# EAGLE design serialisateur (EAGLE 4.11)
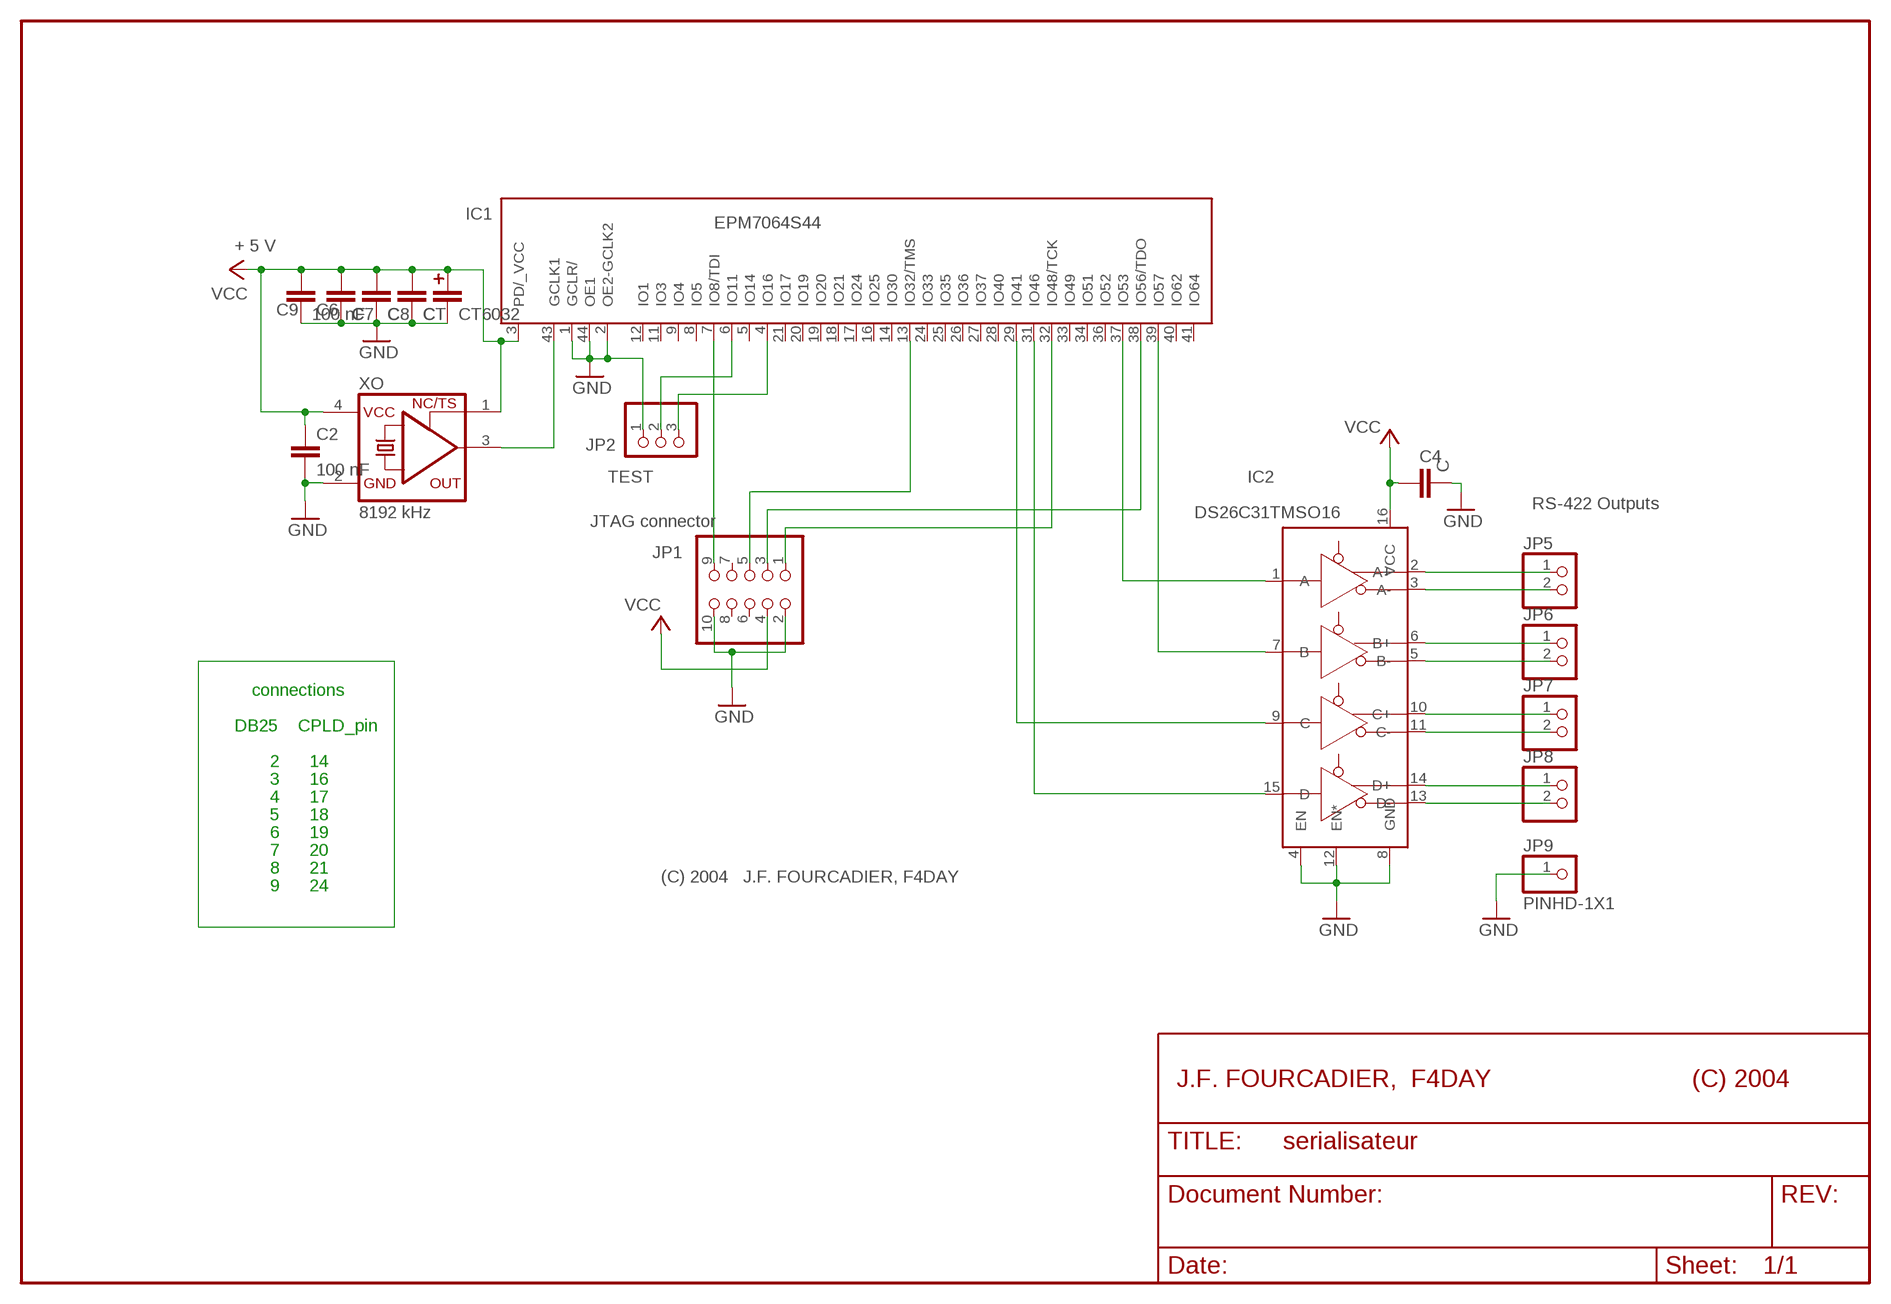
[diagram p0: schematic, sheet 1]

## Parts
C2  100 nF  C1206  [C1206]
C4  C  C1206  [C1206]
C6  C  C1206  [C1206]
C7  C  C1206  [C1206]
C8  C  C1206  [C1206]
C9  100 nF  C1206  [C1206]
CT  CT6032  [CT6032]
IC1  EPM7064S44  EPM7064S44_2  [PLCC-S44_2]
IC2  DS26C31TMSO16  [SO16]
JP1  PINHD-2X5  [2X05]
JP2  PINHD-1X3D  [1X03]
JP5  PINHD-1X2D  [1X02]
JP6  PINHD-1X2D  [1X02]
JP7  PINHD-1X2D  [1X02]
JP8  PINHD-1X2D  [1X02]
JP9  PINHD-1X1  [1X01]
XO  8192 kHz  XO-1100S  [1100S]

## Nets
GND: C2.2 C4.2 C6.2 C7.2 C8.2 C9.2 CT.- IC1.1(GCLR/) IC1.2(OE2-GCLK2) IC1.44(OE1) IC2.4(EN) IC2.8(GND) IC2.12(EN*) JP1.2 JP1.10 JP2.1 JP9.1 XO.2(GND)
N$1: IC1.32(IO48/TCK) JP1.1
N$2: IC1.38(IO56/TDO) JP1.3
N$3: IC1.13(IO32/TMS) JP1.5
N$4: IC1.7(IO8/TDI) JP1.9
N$5: IC1.39(IO57) IC2.7(B)
N$6: IC1.31(IO46) IC2.15(D)
N$7: IC1.37(IO53) IC2.1(A)
N$8: IC2.2(A+) JP5.1
N$9: IC2.3(A-) JP5.2
N$10: IC1.29(IO41) IC2.9(C)
N$11: IC2.6(B+) JP6.1
N$12: IC1.43(GCLK1) XO.3(OUT)
N$13: IC1.4(IO16) JP2.3
N$14: IC1.6(IO11) JP2.2
N$15: IC2.11(C-) JP7.2
N$16: IC2.14(D+) JP8.1
N$17: IC2.13(D-) JP8.2
N$53: IC2.5(B-) JP6.2
N$54: IC2.10(C+) JP7.1
VCC: C2.1 C4.1 C6.1 C7.1 C8.1 C9.1 CT.+ IC1.3(PD/_VCC) IC2.16(VCC) JP1.4 XO.1(TS) XO.4(VCC)
Unconnected: IC1.5(IO14) IC1.8(IO5) IC1.9(IO4) IC1.11(IO3) IC1.12(IO1) IC1.14(IO30) IC1.16(IO25) IC1.17(IO24) IC1.18(IO21) IC1.19(IO20) IC1.20(IO19) IC1.21(IO17) IC1.24(IO33) IC1.25(IO35) IC1.26(IO36) IC1.27(IO37) IC1.28(IO40) IC1.33(IO49) IC1.34(IO51) IC1.36(IO52) IC1.40(IO62) IC1.41(IO64) JP1.6 JP1.7 JP1.8

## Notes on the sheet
- + 5 V
- TEST
- RS-422 Outputs
- JTAG connector
- connections
- DB25    CPLD_pin
- 2      14
- 3      16
- 4      17
- 5      18
- 6      19
- 7      20
- 8      21
- (C) 2004   J.F. FOURCADIER, F4DAY
- 9      24

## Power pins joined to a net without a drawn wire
GND: IC1.10(GND) IC1.22(GND) IC1.30(GND) IC1.42(GND)
VCC: IC1.15(VCC) IC1.23(VCC) IC1.35(VCC)

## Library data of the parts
C2 C4 C6-C9 = capacitor-smd:C
CT = capacitor-smd:CT
IC1 = altera:EPM7064: EPM7064 MAX 7000 family
IC2 = national:DS26C31TM
JP1 = pinhead:PINHD-2X5: PIN HEADER
JP2 = pinhead:PINHD-1X3: PIN HEADER
JP5-JP8 = pinhead:PINHD-1X2: PIN HEADER
JP9 = pinhead:PINHD-1X1: PIN HEADER
XO = crystal:XO-: CRYSTAL

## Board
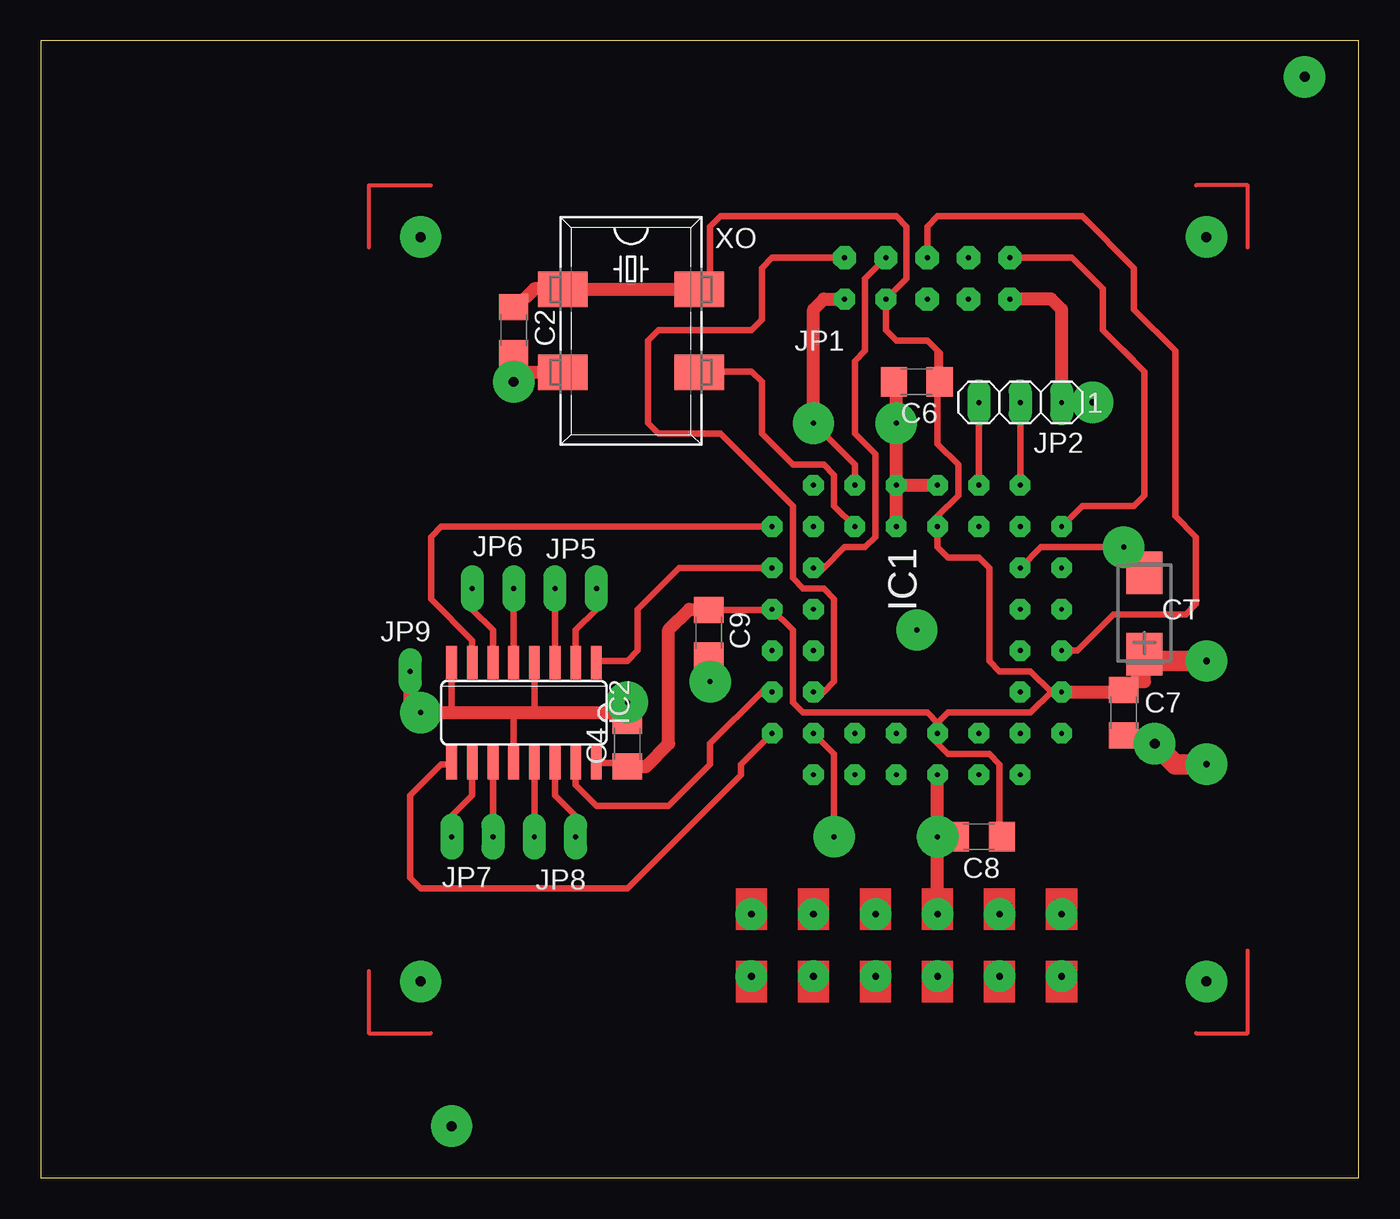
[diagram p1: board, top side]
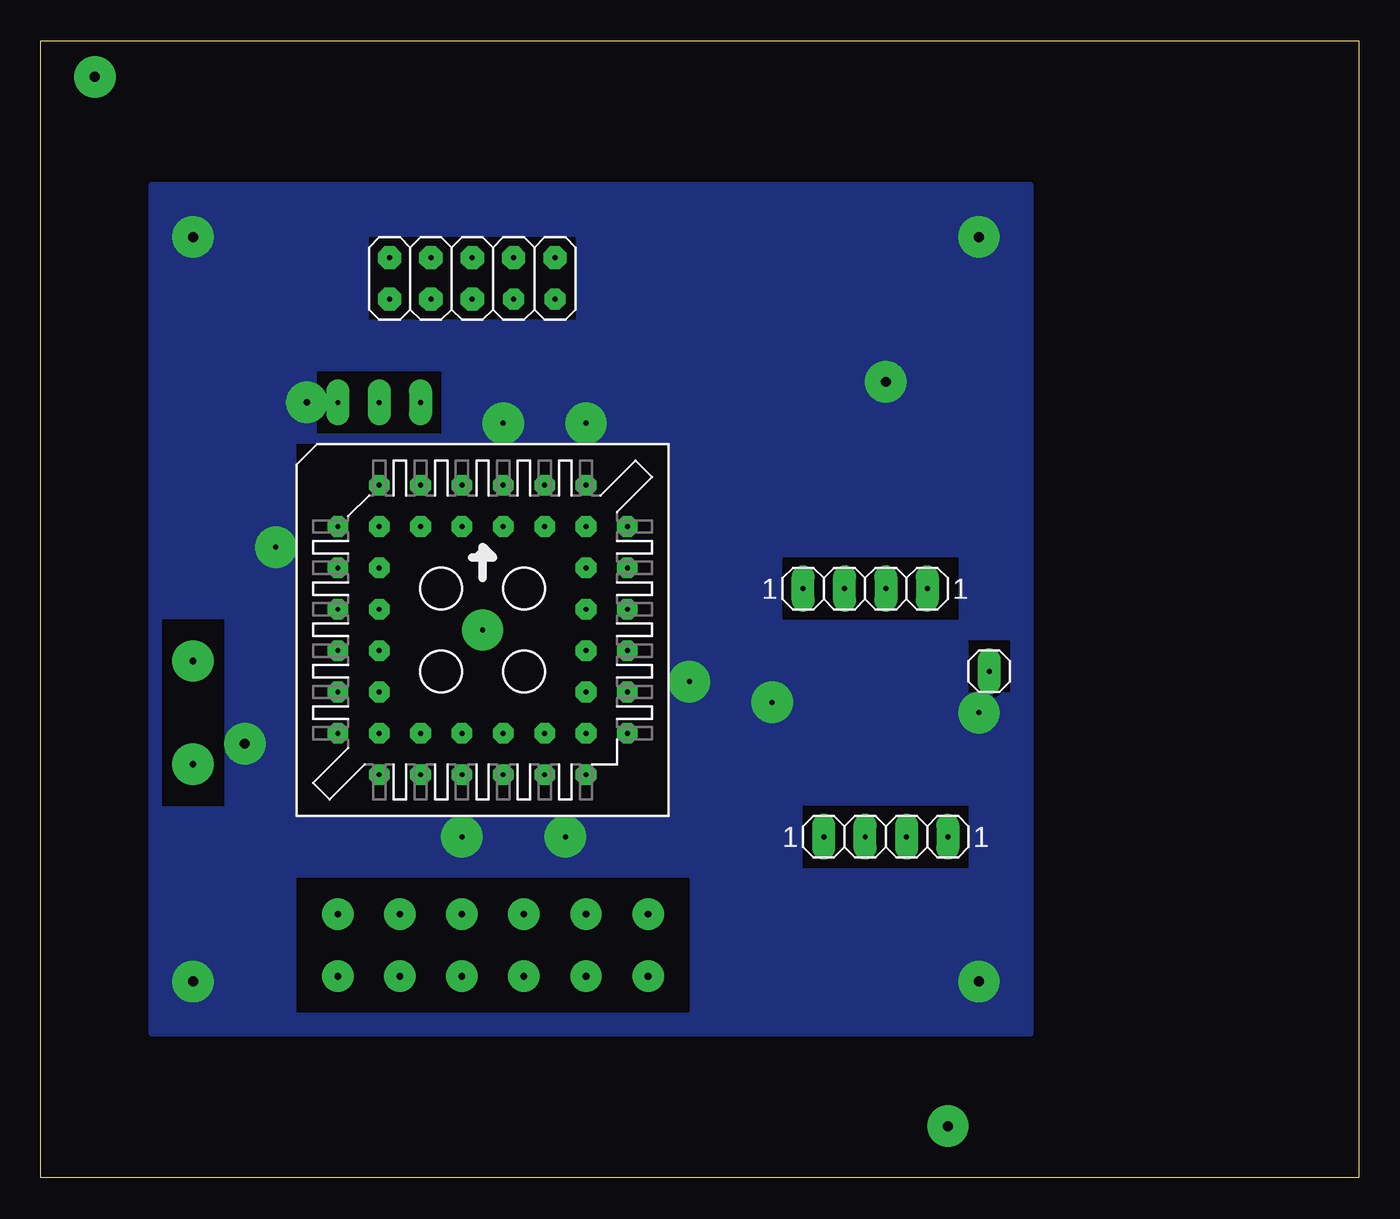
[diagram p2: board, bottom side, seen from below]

Size 80.95 x 69.84 mm. Coordinates in mm from the lower left corner, seen from the top.
Outline: 0,0 80.95,0 80.95,69.84 0,69.84 0,0
Copper layers (1*16): Top 0.035mm / dielectric 1.5mm / GND 0.035mm
Design rules "default": minimum track width 10mil, minimum drill 24mil, track to track 8mil, track to pad 8mil, pad to pad 8mil, via to via 8mil, smd to smd 8mil, copper to edge 40mil, drill to drill 8mil, minimum pad ring 10mil, minimum via ring 8mil, stop-mask expansion 4mil, vias tented up to drill 0mil, thermal gap 10mil
bRestrict: area 42.4,22.2 to 65.2,45.1; area 48.1,52.7 to 60.8,57.8; area 24.6,34.3 to 30.3,38.1; area 30.3,34.3 to 35.4,38.1; area 24,19 to 29,22.9; area 29,19 to 34.1,22.9; area 69.7,22.9 to 73.5,34.3; area 41.1,10.2 to 65.2,18.4; area 56.3,45.7 to 64,49.5; area 21.4,29.8 to 24,33

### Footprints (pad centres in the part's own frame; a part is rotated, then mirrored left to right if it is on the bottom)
C1206 = smd 1.6 x 1.8: 1 -1.4,0; 2 1.4,0
CT6032 = smd 2.6 x 2.2: + -2.5,0; - 2.5,0
PLCC-S44_2 = drill 0.305 pad 1.27 octagon: 1 1.27,6.35; 2 -1.27,8.89; 3 -1.27,6.35; 4 -3.81,8.89; 5 -3.81,6.35; 6 -6.35,8.89; 7 -8.89,6.35; 8 -6.35,6.35; 9 -8.89,3.81; 10 -6.35,3.81; 11 -8.89,1.27; 12 -6.35,1.27; 13 -8.89,-1.27; 14 -6.35,-1.27; 15 -8.89,-3.81; 16 -6.35,-3.81; 17 -8.89,-6.35; 18 -6.35,-8.89; 19 -6.35,-6.35; 20 -3.81,-8.89; 21 -3.81,-6.35; 22 -1.27,-8.89; 23 -1.27,-6.35; 24 1.27,-8.89; 25 1.27,-6.35; 26 3.81,-8.89; 27 3.81,-6.35; 28 6.35,-8.89; 29 8.89,-6.35; 30 6.35,-6.35; 31 8.89,-3.81; 32 6.35,-3.81; 33 8.89,-1.27; 34 6.35,-1.27; 35 8.89,1.27; 36 6.35,1.27; 37 8.89,3.81; 38 6.35,3.81; 39 8.89,6.35; 40 6.35,8.89; 41 6.35,6.35; 42 3.81,8.89; 43 3.81,6.35; 44 1.27,8.89
SO16 = smd 0.66 x 2.032: 1 -0.635,-3.073; 2 0.635,-3.073; 3 1.905,-3.073; 4 3.175,-3.073; 5 4.445,-3.073; 6 5.715,-3.073; 7 6.985,-3.073; 8 8.255,-3.073; 9 8.255,3.073; 10 6.985,3.073; 11 5.715,3.073; 12 4.445,3.073; 13 3.175,3.073; 14 1.905,3.073; 15 0.635,3.073; 16 -0.635,3.073
2X05 = drill 0.305 pad 1.422 octagon: 1 -5.08,-1.27; 3 -2.54,-1.27; 5 0,-1.27; 6 0,1.27; 7 2.54,-1.27; 8 2.54,1.27; 9 5.08,-1.27; 10 5.08,1.27 | drill 0.305 pad 1.27 octagon: 2 -5.08,1.27; 4 -2.54,1.27
1X03 = drill 0.305 pad 1.422 long: 1 -2.54,0; 2 0,0; 3 2.54,0
1X02 = drill 0.305 pad 1.422 long: 1 -1.27,0; 2 1.27,0
1X01 = drill 0.305 pad 1.422 long: 1 0,0
1100S = smd 2.184 x 3.048: 1 -2.54,-4.191; 2 2.54,-4.191; 3 2.54,4.191; 4 -2.54,4.191

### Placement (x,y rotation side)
C2  29.05,52.06 270 top
C4  36.03,26.66 90 top
C6  53.81,48.89 180 top
C7  66.51,28.57 270 top
C8  57.62,20.95 180 top
C9  41.02,33.47 270 top
CT  67.78,34.67 90 top
IC1  53.81,33.65 0 bottom
IC2  33.49,28.57 180 top
JP1  54.45,55.24 180 bottom
JP2  60.16,47.62 180 top
JP5  32.85,36.19 0 bottom
JP6  27.77,36.19 180 bottom
JP7  26.5,20.95 180 bottom
JP8  31.59,20.95 0 bottom
JP9  22.7,31.11 0 bottom
XO  36.26,52.01 270 top

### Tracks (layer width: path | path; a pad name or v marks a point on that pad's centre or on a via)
GND  (via drill 0.3 pad 2.54, 0.41 pad 1.93, 0.41 pad 2.54, 0.61 pad 2.54)
  Top 0.406: 30.31,31.74 IC2.4 30.31,28.57 29.05,28.57 IC2.12 | 25.23,28.57 IC2.8 | IC1.30 48.73,26.03 v48.73,20.95 | v47.46,46.35 50,43.81 IC1.42 | C6.2 52.41,46.48 v52.54,46.35 | v66.51,38.73 61.43,38.73 IC1.10
  Top 0.813: JP9.1 22.7,29.2 v23.33,28.57 25.23,28.57 29.05,28.57 36.03,28.57 | v41.11,30.47 41.02,30.56 C9.2 | v55.08,20.95 IC1.22 | v55.08,20.95 C8.2 | 29.05,50.8 C2.2 29.05,49.52 | XO.2 29.1,49.47 29.05,49.52 | v29.05,48.89 29.05,49.52 | v68.41,26.66 67.91,27.17 C7.2 | JP1.2 48.09,53.97 47.46,53.34 v47.46,46.35 | C6.2 52.54,48.89 v52.54,46.35 IC1.44 | IC1.44 IC1.2 | IC1.1 IC1.44 | v66.51,38.73 CT.- | JP1.10 62.06,53.97 62.7,53.34 JP2.1 v64.61,47.62 | 36.03,28.57 C4.2 | 36.03,28.57 v36.03,29.2 | v55.08,16.19 v55.08,20.95
  Top 1.27: v68.41,26.66 69.69,25.39 v71.59,25.39
  other vias: 23.33,12.06 23.33,57.78 71.59,12.06 71.59,57.78
  pour GND: 20.16,60.95 20.16,8.88 74.13,8.88 74.13,60.95
N$1
  Top 0.406: IC1.32 48.09,29.84 48.73,30.47 48.73,35.55 48.09,36.19 46.82,36.19 46.19,36.83 46.19,41.27 41.74,45.71 37.93,45.71 37.3,46.35 37.3,51.43 37.93,52.06 43.65,52.06 44.28,52.7 44.28,55.88 44.92,56.51 JP1.1
N$2
  Top 0.406: IC1.38 48.09,37.46 49.36,38.73 50.63,38.73 51.27,39.37 51.27,44.45 50,45.71 50,50.16 50.63,50.8 50.63,55.24 JP1.3
N$3
  Top 0.406: IC1.13 63.65,32.38 65.88,34.6 70.32,34.6 70.95,35.24 70.95,39.37 69.69,40.63 69.69,50.8 67.14,53.34 67.14,55.88 63.97,59.05 55.08,59.05 54.45,58.41 JP1.5
N$4
  Top 0.406: 67.78,49.52 65.24,52.06 65.24,54.6 63.33,56.51 JP1.9 | 67.78,49.52 67.78,41.91 67.14,41.27 63.97,41.27 IC1.7 | 67.78,49.52 66.51,50.8
N$5
  Top 0.406: 41.74,40 IC1.39 24.6,40 23.96,39.37 23.96,35.55 26.5,33.02 IC2.7
N$6
  Top 0.406: IC2.15 32.85,24.12 34.12,22.86 38.57,22.86 41.11,25.39 41.11,26.66 44.28,29.84 IC1.31
N$7
  Top 0.406: IC1.37 39.2,37.46 36.66,34.92 36.66,32.38 36.03,31.74 34.12,31.74 IC2.1
N$8
  Top 0.406: IC2.2 32.85,33.65 34.12,34.92 JP5.1
N$9
  Top 0.406: IC2.3 JP5.2
N$10
  Top 0.406: 39.2,20.95 39.84,21.59 | IC1.29 43.02,25.39 43.02,24.76 39.2,20.95 | IC2.9 25.23,25.39 24.6,25.39 22.7,23.49 22.7,18.41 23.33,17.77 36.03,17.77 39.2,20.95
N$11
  Top 0.406: JP6.1 26.5,34.92 27.77,33.65 IC2.6
N$12
  Top 0.406: IC1.43 48.73,41.27 48.73,43.17 48.09,43.81 46.19,43.81 44.28,45.71 44.28,48.89 43.65,49.52 40.48,49.52 40.45,49.5 XO.3
N$13
  Top 0.406: IC1.4 JP2.3
N$14
  Top 0.406: IC1.6 JP2.2
N$15
  Top 0.406: JP7.2 IC2.11
N$16
  Top 0.406: JP8.1 32.85,22.22 31.59,23.49 IC2.14
N$17
  Top 0.406: JP8.2 IC2.13
N$18  (via drill 0.41 pad 1.93)
  other vias: 47.46,16.19 47.46,16.19
N$19  (via drill 0.41 pad 1.93)
  other vias: 51.27,16.19
N$20  (via drill 0.41 pad 1.93)
  other vias: 58.89,16.19
N$21  (via drill 0.41 pad 1.93)
  other vias: 62.7,16.19
N$22  (via drill 0.41 pad 1.93)
  other vias: 47.46,12.38
N$23  (via drill 0.41 pad 1.93)
  other vias: 51.27,12.38
N$24  (via drill 0.41 pad 1.93)
  other vias: 55.08,12.38
N$25
  Top 0.254: 20.16,57.14 20.16,60.95 23.96,60.95
N$26
  Top 0.254: 70.95,60.95 74.13,60.95 74.13,57.14
N$27
  Top 0.254: 20.16,12.7 20.16,8.88 23.96,8.88
N$28
  Top 0.254: 70.95,8.88 74.13,8.88 74.13,13.96
N$29  (via drill 0.3 pad 2.54)
  other vias: 53.81,33.65
N$30  (via drill 0.61 pad 2.54)
  other vias: 77.62,67.62
N$31  (via drill 0.61 pad 2.54)
  other vias: 25.23,3.17
N$32  (via drill 0.41 pad 1.93)
  other vias: 58.89,12.38
N$33  (via drill 0.41 pad 1.93)
  other vias: 62.7,12.38
N$34  (via drill 0.41 pad 1.93)
  other vias: 43.65,16.19
N$35  (via drill 0.41 pad 1.93)
  other vias: 43.65,12.38
N$53
  Top 0.406: 29.05,36.51 JP6.2 IC2.5
N$54
  Top 0.406: IC2.10 26.5,23.49 25.23,22.22 JP7.1
VCC  (via drill 0.41 pad 2.54)
  Top 0.406: 39.84,54.6 39.81,54.58 XO.4 40.45,54.58 40.48,54.6 41.11,54.6 41.11,58.41 41.74,59.05 52.54,59.05 53.17,58.41 53.17,55.24 JP1.4 51.91,52.06 52.54,51.43 54.45,51.43 55.08,50.8 | C6.1 55.21,50.66 55.08,50.8 | 55.08,50.8 55.08,45.08 56.35,43.81 56.35,41.91 55.08,40.63 IC1.3 55.08,38.73 55.72,38.09 57.62,38.09 58.25,37.46 58.25,31.74 58.89,31.11 60.8,31.11 62.06,29.84 | C8.1 58.89,20.95 58.89,25.39 58.25,26.03 55.72,26.03 55.08,26.66 IC1.23 55.08,27.93 | 62.06,29.84 IC1.15 | 62.06,29.84 60.8,28.57 55.72,28.57 55.08,27.93 | 55.08,27.93 54.45,28.57 46.82,28.57 46.19,29.2 46.19,33.65 IC1.35 44.87,34.87 41.11,34.87 C9.1 | C4.1 36.03,25.5 IC2.16
  Top 0.813: C2.1 29.17,53.46 30.31,54.6 32.22,54.6 32.22,54.55 | 32.22,54.55 XO.1 | 32.22,54.55 39.15,54.55 39.18,54.58 | 39.18,54.58 39.2,54.6 | XO.4 39.18,54.58 | C7.1 66.64,29.97 67.78,31.11 | 67.78,31.11 67.78,31.74 CT.+ | 67.78,31.11 67.78,30.47 67.14,30.47 66.51,29.84 IC1.15 | 41.11,34.87 41.11,34.92 39.84,34.92 38.57,33.65 38.57,26.66 37.17,25.27 C4.1
  Top 1.27: 67.78,31.74 v71.59,31.74
(copper drawn outside any net)
  shapes: Top area x12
